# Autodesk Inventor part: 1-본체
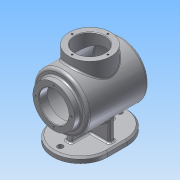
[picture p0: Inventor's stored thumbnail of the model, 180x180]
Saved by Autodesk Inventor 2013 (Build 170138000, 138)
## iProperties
Created: 2016-04
Part Number: 1-본체
Material: 알루미늄 6061
Document SubType Name: Modeling
Designer: Administrator
Density: 2.71 g/cm^3
Mass: 936.549 g
Surface Area: 1291.45 cm^2
Volume: 345.59 cm^3
Author: Administrator
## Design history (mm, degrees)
sketch "스케치1"
  geometry: L1 (-17.5, 50)-(17.5, 50); L2 (17.5, -50)-(-17.5, -50); A1 r 50 centre (17.5, 0) between (17.5, -50) and (17.5, 50); A2 r 50 centre (-17.5, 0) between (-17.5, 50) and (-17.5, -50); 2 further points
  constraints: 4 end point, 4 point on circle, 2 centre point, 2 horizontal alignment, 2 tangent, 1 equal radius, 1 horizontal, 1 midpoint, 1 parallel, 1 vertical alignment
  dimensions: "d86" = 100 distance of L2.start L1.end; "d88" = 135 dimension on A1 A2
extrude "돌출1" new body sketch "스케치1" distance "d3" = 10; taper "d4" = 0 deg
node "작업 평면2"
sketch "스케치10"
  geometry: L1 (-65.924, 79)-(65.924, 79); L2 (-65.924, 79)-(-65.924, 117); L3 (-65.924, 117)-(-53.924, 117); L4 (-53.924, 117)-(-53.924, 129); L5 (-53.924, 129)-(56.076, 129); L6 (17.5, 0)-(-17.5, 0) reference; A1 r 131.848 centre (-65.924, 79) between (65.924, 79) and (56.076, 129); 3 further points
  constraints: 10 end point, 2 midpoint, 2 parallel, 2 point on circle, 2 vertical alignment, 1 centre point, 1 coincident, 1 horizontal, 1 perpendicular
  dimensions: "d48" = 76 diameter of L3 L1; "d49" = 12 distance of L2.end L3.end; "d50" = 100 diameter of L5 L1; "d53" = 110 horizontal distance of L5.end L3.end; "d90" = 158 diameter of L6 L1
revolve "회전2" sketch "스케치10" stored, may be unused: angle "d55" = 90 deg
sketch "스케치11"
  geometry: L1 (-53.924, 29)-(-53.924, 129) reference; L2 (55.544, 29)-(55.544, 129) reference; L3 (-53.924, 129)-(56.076, 129) reference; L4 (-53.924, 29)-(56.076, 29) reference; L5 (-50.924, 126)-(53.601, 126); L6 (-50.924, 79)-(-50.924, 126); L7 (-50.924, 79)-(63.456, 79); A1 r 117 centre (-53.544, 79) between (63.456, 79) and (53.601, 126); 6 further points; 1 other entity
  constraints: 6 end point, 2 horizontal alignment, 2 parallel, 2 point on circle, 1 centre point, 3 other
  dimensions: "d56" = 3 distance between parallel lines of L3 L5; "d57" = 3 dimension on A1; "d58" = 3 distance between parallel lines of L1 L6
revolve "회전3" sketch "스케치11" stored, may be unused: angle "d60" = 90 deg
hole "구멍2" diameter "d63" = 54; stored, may be unused: countersink angle "d67" = 90 deg, drill point angle "d69" = 0 deg; dims "d61" = 10, "d62" = 10, "d64" = 6, "d65" = 54, "d66" = 15, "d68" = 15
node "작업 평면3"
sketch "스케치12"
  geometry: C1 r 38 at (0, 0); 1 further point
  constraints: 1 centre point, 1 coincident
  dimensions: "d71" = 76 diameter of C1
extrude "돌출6" join sketch "스케치12" stored distance "d73" = 15; taper "d74" = 0 deg
hole "구멍3" diameter "d77" = 54; stored, may be unused: countersink angle "d81" = 90 deg, drill point angle "d83" = 0 deg; dims "d75" = 10, "d76" = 10, "d78" = 6, "d79" = 54, "d80" = 15, "d82" = 30
sketch "스케치14"
  geometry: 3 further points
  constraints: 2 horizontal alignment
  dimensions: "d91" = 54 distance of point (0, 0) point (-54, 0); "d92" = 54 distance of point (54, 0) point (0, 0)
hole "구멍4" sketch "스케치14" at (-54, 0), (54, 0) diameter "d93" = 10; stored, may be unused: countersink angle "d97" = 90 deg, drill point angle "d99" = 0 deg; dims "d94" = 6, "d95" = 54, "d96" = 15, "d98" = 30
sketch "스케치16"
  geometry: L1 (50, 10)-(-50, 10) reference; L2 (-40, 10)-(-40, 49); L3 (40, 49)-(40, 10); A1 r 50 centre (0, 79) between (-40, 49) and (40, 49) reference; 1 further point
  constraints: 4 end point, 2 point on circle, 2 point on line
  dimensions: "d105" = 90 deg angle of L1 L2; "d106" = 40 horizontal distance of point (0, 0) L2.start; "d107" = 40 horizontal distance of point (0, 0) L3.end; "d108" = 90 deg angle of L1 L3
extrude "돌출8" join sketch "스케치16" stored distance "d109" = 10; taper "d110" = 0 deg
sketch "스케치17"
  geometry: L1 (-53.924, 29)-(56.076, 29) reference; L2 (-17.5, 10)-(-67.5, 10) reference; L3 (67.5, 10)-(17.5, 10) reference; L4 (-36.65, 29)-(-40, 10); L5 (36.65, 29)-(40, 10); 1 further point
  constraints: 4 end point, 4 point on line
  dimensions: "d111" = 40 horizontal distance of L4.end point (0, 0); "d112" = 40 horizontal distance of L5.end point (0, 0); "d113" = 100 deg angle of L2 L4; "d114" = 100 deg angle of L3 L5
feature "리브1" dims "d115" = 1, "d116" = 10, "d117" = 0, "d118" = 0, "d119" = 1, "d120" = 1
feature "리브2" dims "d121" = 1, "d122" = 10, "d123" = 0, "d124" = 0, "d125" = 1, "d126" = 1
sketch "스케치18" dims "d127" = 65
  geometry: C1 r 50 at (0, 0) reference; C2 r 38 at (0, 0) reference; 3 further points
  constraints: 2 vertical alignment, 1 coincident, 2 other
hole "구멍5" sketch "스케치18" at (0, 32.5) diameter "d129" = 3.242; stored, may be unused: countersink angle "d133" = 90 deg, drill point angle "d135" = 0 deg; dims "d130" = 8, "d131" = 54, "d132" = 15, "d134" = 10
sketch "스케치19" dims "d139" = 65
  geometry: 3 further points
  constraints: 2 vertical alignment, 1 coincident, 2 other
hole "구멍6" sketch "스케치19" at (0, 32.5) diameter "d141" = 3.242; stored, may be unused: countersink angle "d145" = 90 deg, drill point angle "d147" = 0 deg; dims "d142" = 8, "d143" = 54, "d144" = 15, "d146" = 10
fillet "모깎기1" dims "d151" = 2
fillet "모깎기2" dims "d152" = 2
fillet "모깎기3" dims "d153" = 5
fillet "모깎기4" dims "d154" = 3
fillet "모깎기5" dims "d155" = 3
chamfer "모따기1" distance "d156" = 1; stored, may be unused: second distance "d157" = 2, angle "d158" = 45 deg
fillet "모깎기6" dims "d159" = 3
fillet "모깎기7" dims "d160" = 3
chamfer "모따기2" distance "d161" = 3; stored, may be unused: second distance "d162" = 2, angle "d163" = 45 deg
node "작업 평면6"
node "솔리드1"
pattern_circular "원형 패턴1" dims angle "d137" = 360 deg
pattern_circular "원형 패턴2" dims angle "d149" = 360 deg
node "투영된 루프4"
node "투영된 루프5"
node "투영된 루프6"
other parameters: "d33" = 144, "d70" = 144
